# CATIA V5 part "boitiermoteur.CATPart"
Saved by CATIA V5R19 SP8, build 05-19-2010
Part number: boitiermoteur
Revision: ANY
Definition: UNKNOWN
Nomenclature: boitiermoteur
Source: Unknown
Bounding box of the stored display mesh (mm): x 119.466 to 156.534, y 7 to 36, z -1 to 13
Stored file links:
  D:\Documents\1_Travail\1 - ac-limoges.fr\ac-limoges.fr\Emmanuel Maynard - STI2D_Turgot\2 -2I2D\2_SEQUENCE_Serrure_Biométrique\5-Spé_ITEC\Serrure_Bio_Eleve\boitiermoteur.CATPart
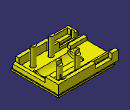
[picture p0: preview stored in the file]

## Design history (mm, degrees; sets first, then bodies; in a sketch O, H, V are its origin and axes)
Body1 "Enlèv. mat.-Extru.11" (main body)
  Solid1: solid without history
